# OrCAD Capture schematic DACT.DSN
size A
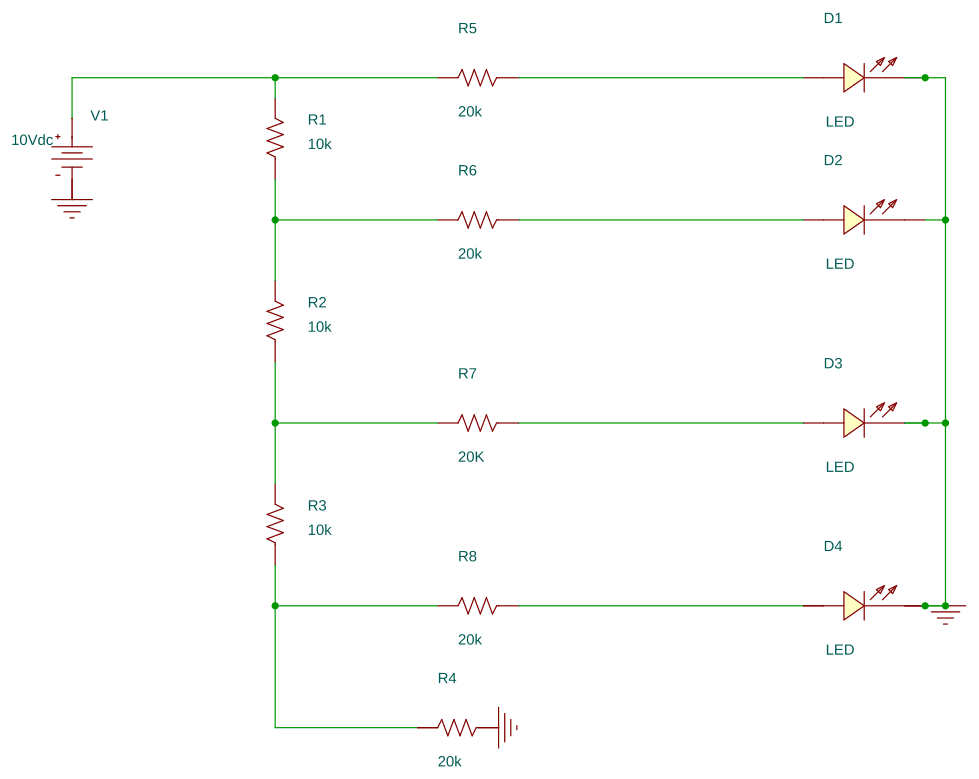
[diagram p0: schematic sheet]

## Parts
D1  LED
D2  LED
D3  LED
D4  LED
R1  10k  [AX/RC05]
R2  10k  [AX/RC05]
R3  10k  [AX/RC05]
R4  20k  [AX/RC05]
R5  20k  [AX/RC05]
R6  20k  [AX/RC05]
R7  20K  [AX/RC05]
R8  20k  [AX/RC05]
V1  VDC

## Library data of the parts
D1-D4 = LED
R1-R8 = r
V1 = VDC: DC: 10Vdc

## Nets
0: D1.1(CATHODE) D2.1(CATHODE) D3.1(CATHODE) D4.1(CATHODE) R4.1 V1.1(-)
N21307: D1.2(ANODE) R5.1
N21313: D4.2(ANODE) R8.1
N21319: D3.2(ANODE) R7.1
N21331: D2.2(ANODE) R6.1
N21403: R1.2 R5.2 V1.0(+)
N21415: R1.1 R2.2 R6.2
N21419: R2.1 R3.2 R7.2
N21423: R3.1 R4.2 R8.2
